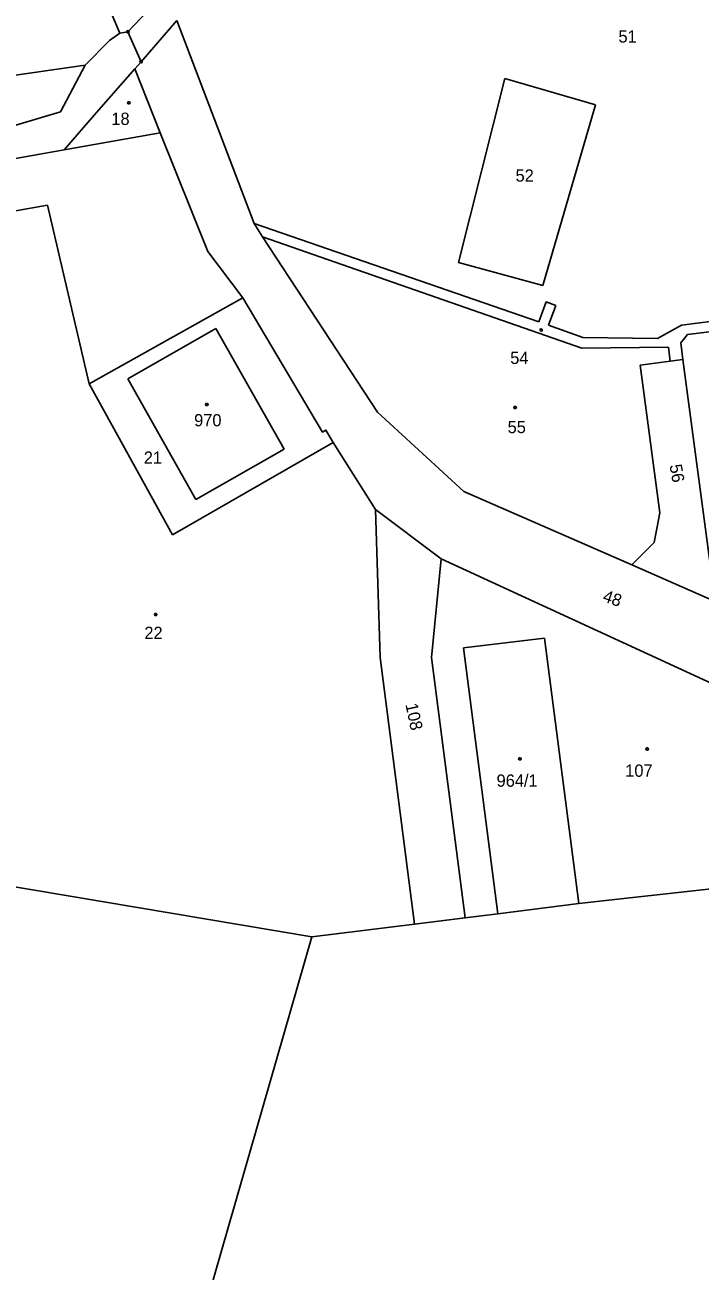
# Model space of a CAD drawing. Extents: x -841286 to -834997, y -1020681 to -1017810.
# Drawn here: x -838632.6 to -838539, y -1019346.4 to -1019173.8 of the extents above; entities that cross this region are included whole.
import ezdxf

# ---------------------------------------------------------------- set-up
doc = ezdxf.new("R2010")
doc.units = 0
for name, color, linetype in [('NERES_SET', 7, 'Continuous'), ('OVNE_POP', 7, 'Continuous'), ('OVNE_PRE', 7, 'Continuous'), ('OVNE_SET', 7, 'Continuous'), ('OVNI_PRE', 7, 'Continuous'), ('OVNI_SET', 7, 'Continuous')]:
    doc.layers.add(name, color=color, linetype=linetype)

msp = doc.modelspace()

# ---------------------------------------------------------------- linework, layer by layer
at = {"layer": 'NERES_SET'}
msp.add_line((-838560.96, -1019215.91), (-838561.05, -1019216.03), dxfattribs=at)
msp.add_lwpolyline([(-838561.21, -1019216.1), (-838561.2, -1019215.92), (-838561.03, -1019215.86), (-838560.89, -1019215.96), (-838560.9, -1019216.14), (-838561.07, -1019216.2)], close=True, dxfattribs=at)
at = {"layer": 'OVNE_POP'}
for points in [[(-838618.1, -1019184.43), (-838618.01, -1019184.58), (-838618.1, -1019184.73), (-838618.28, -1019184.73), (-838618.37, -1019184.58), (-838618.28, -1019184.43)], [(-838564.58, -1019226.62), (-838564.49, -1019226.77), (-838564.58, -1019226.92), (-838564.76, -1019226.92), (-838564.85, -1019226.77), (-838564.76, -1019226.62)], [(-838614.38, -1019255.3), (-838614.29, -1019255.45), (-838614.38, -1019255.6), (-838614.56, -1019255.6), (-838614.65, -1019255.45), (-838614.56, -1019255.3)], [(-838546.27, -1019273.95), (-838546.18, -1019274.1), (-838546.27, -1019274.25), (-838546.45, -1019274.25), (-838546.54, -1019274.1), (-838546.45, -1019273.95)]]:
    msp.add_lwpolyline(points, close=True, dxfattribs=at)
at = {"layer": 'OVNE_SET'}
for p, q in [((-838631.42, -1019146.42), (-838619.46, -1019174.91)), ((-838600.81, -1019201.29), (-838611.56, -1019173.14)), ((-838619.46, -1019174.91), (-838620.89, -1019175.92)), ((-838618.31, -1019174.72), (-838619.46, -1019174.91)), ((-838616.49, -1019178.87), (-838618.31, -1019174.72)), ((-838620.89, -1019175.92), (-838624.25, -1019179.33)), ((-838624.25, -1019179.33), (-838648.88, -1019182.92)), ((-838627.66, -1019185.82), (-838624.25, -1019179.33)), ((-838622.69, -1019185.93), (-838617.38, -1019179.88)), ((-838617.38, -1019179.88), (-838616.49, -1019178.87)), ((-838617.38, -1019179.88), (-838613.83, -1019188.73)), ((-838572.49, -1019206.71), (-838566.07, -1019181.19)), ((-838566.07, -1019181.19), (-838553.5, -1019184.84)), ((-838553.5, -1019184.84), (-838560.83, -1019209.9)), ((-838641.09, -1019189.82), (-838627.66, -1019185.82)), ((-838627.16, -1019191.1), (-838622.69, -1019185.93)), ((-838613.83, -1019188.73), (-838627.16, -1019191.1)), ((-838607.22, -1019205.18), (-838613.83, -1019188.73)), ((-838627.16, -1019191.1), (-838637.66, -1019192.97)), ((-838644, -1019201.34), (-838629.48, -1019198.76)), ((-838629.48, -1019198.76), (-838623.67, -1019223.48)), ((-838600.81, -1019201.29), (-838599.68, -1019203.13)), ((-838561.37, -1019214.91), (-838600.81, -1019201.29)), ((-838599.68, -1019203.13), (-838555.41, -1019218.55)), ((-838583.74, -1019227.43), (-838599.68, -1019203.13)), ((-838602.37, -1019211.59), (-838607.22, -1019205.18)), ((-838560.83, -1019209.9), (-838572.49, -1019206.71)), ((-838623.67, -1019223.48), (-838602.37, -1019211.59)), ((-838602.37, -1019211.59), (-838591.34, -1019230.19)), ((-838560.34, -1019212.14), (-838561.37, -1019214.91)), ((-838559, -1019212.65), (-838560.34, -1019212.14)), ((-838560.04, -1019215.36), (-838559, -1019212.65)), ((-838520.89, -1019212.74), (-838541.6, -1019215.35)), ((-838540.79, -1019216.68), (-838520.8, -1019214.17)), ((-838606.13, -1019215.85), (-838618.35, -1019222.83)), ((-838596.65, -1019232.57), (-838606.13, -1019215.85)), ((-838555.27, -1019217.09), (-838560.04, -1019215.36)), ((-838541.6, -1019215.35), (-838544.94, -1019217.22)), ((-838544.94, -1019217.22), (-838555.27, -1019217.09)), ((-838541.71, -1019217.83), (-838540.79, -1019216.68)), ((-838541.4, -1019220.14), (-838541.71, -1019217.83)), ((-838555.41, -1019218.55), (-838543.4, -1019218.43)), ((-838543.4, -1019218.43), (-838543.16, -1019220.38)), ((-838543.16, -1019220.38), (-838547.35, -1019220.93)), ((-838547.35, -1019220.93), (-838544.63, -1019241.37)), ((-838543.16, -1019220.38), (-838541.4, -1019220.14)), ((-838536.94, -1019253.66), (-838541.4, -1019220.14)), ((-838618.35, -1019222.83), (-838608.89, -1019239.51)), ((-838623.67, -1019223.48), (-838612.15, -1019244.4)), ((-838571.76, -1019238.43), (-838583.74, -1019227.43)), ((-838591.34, -1019230.19), (-838590.88, -1019229.92)), ((-838590.88, -1019229.92), (-838589.89, -1019231.61)), ((-838612.15, -1019244.4), (-838589.89, -1019231.61)), ((-838589.89, -1019231.61), (-838584.01, -1019240.89)), ((-838608.89, -1019239.51), (-838596.65, -1019232.57)), ((-838548.51, -1019248.6), (-838571.76, -1019238.43)), ((-838574.9, -1019247.75), (-838584.01, -1019240.89)), ((-838584.01, -1019240.89), (-838583.37, -1019261.43)), ((-838544.63, -1019241.37), (-838545.38, -1019245.5)), ((-838545.38, -1019245.5), (-838548.51, -1019248.6)), ((-838576.23, -1019261.4), (-838574.9, -1019247.75)), ((-838574.9, -1019247.75), (-838527.61, -1019269.56)), ((-838548.51, -1019248.6), (-838536.94, -1019253.66)), ((-838560.58, -1019258.74), (-838571.83, -1019260.07)), ((-838555.84, -1019295.51), (-838560.58, -1019258.74)), ((-838571.83, -1019260.07), (-838567.07, -1019296.91)), ((-838583.37, -1019261.43), (-838578.6, -1019298.35)), ((-838571.57, -1019297.47), (-838576.23, -1019261.4)), ((-838592.81, -1019300.12), (-838639.19, -1019292.34)), ((-838536.26, -1019293.35), (-838555.84, -1019295.51)), ((-838567.07, -1019296.91), (-838555.84, -1019295.51)), ((-838578.6, -1019298.35), (-838571.57, -1019297.47)), ((-838567.07, -1019296.91), (-838571.57, -1019297.47)), ((-838578.6, -1019298.35), (-838592.81, -1019300.12)), ((-838615.45, -1019378.71), (-838592.81, -1019300.12))]:
    msp.add_line(p, q, dxfattribs=at)
at = {"layer": 'OVNI_PRE'}
for points in [[(-838607.3, -1019226.21), (-838607.21, -1019226.36), (-838607.3, -1019226.51), (-838607.48, -1019226.51), (-838607.57, -1019226.36), (-838607.48, -1019226.21)], [(-838563.9, -1019275.31), (-838563.81, -1019275.46), (-838563.9, -1019275.61), (-838564.08, -1019275.61), (-838564.17, -1019275.46), (-838564.08, -1019275.31)]]:
    msp.add_lwpolyline(points, close=True, dxfattribs=at)
at = {"layer": 'OVNI_SET'}
for p, q in [((-838618.31, -1019174.72), (-838613.36, -1019169.5)), ((-838611.56, -1019173.14), (-838616.49, -1019178.87))]:
    msp.add_line(p, q, dxfattribs=at)
for points in [[(-838618.14, -1019174.74), (-838618.24, -1019174.88), (-838618.41, -1019174.86), (-838618.48, -1019174.7), (-838618.38, -1019174.56), (-838618.21, -1019174.58)], [(-838616.48, -1019178.7), (-838616.33, -1019178.79), (-838616.34, -1019178.96), (-838616.5, -1019179.04), (-838616.65, -1019178.95), (-838616.64, -1019178.78)]]:
    msp.add_lwpolyline(points, close=True, dxfattribs=at)
msp.add_lwpolyline([(-838612.15, -1019244.4), (-838589.89, -1019231.61), (-838590.88, -1019229.92), (-838591.34, -1019230.19), (-838602.37, -1019211.59), (-838623.67, -1019223.48), (-838612.15, -1019244.4)], dxfattribs=at)

# ---------------------------------------------------------------- texts
at = {"layer": 'NERES_SET'}
msp.add_text('54', height=1.7, dxfattribs=at).set_placement((-838565.34, -1019220.75))
at = {"layer": 'OVNE_PRE'}
for s, height, p in [('51', 1.7, (-838550.34, -1019176.22)), ('18', 1.7, (-838620.61, -1019187.63)), ('52', 1.7, (-838564.6, -1019195.49)), ('54', 0.1, (-838561.05, -1019215.91)), ('970', 1.7, (-838609.14, -1019229.39)), ('55', 1.7, (-838565.7, -1019230.33)), ('21', 1.7, (-838616.12, -1019234.57)), ('22', 1.7, (-838616.04, -1019258.85)), ('107', 1.7, (-838549.4, -1019277.94)), ('964/1', 1.7, (-838567.23, -1019279.32))]:
    msp.add_text(s, height=height, dxfattribs=at).set_placement(p)
for s, rotation, p in [('56', 280.0045, (-838543.27, -1019234.79)), ('48', 340.6234, (-838552.64, -1019253.59)), ('108', 281.8379, (-838579.87, -1019267.92))]:
    msp.add_text(s, height=1.7, rotation=rotation, dxfattribs=at).set_placement(p)

doc.saveas('drawing.dxf')
